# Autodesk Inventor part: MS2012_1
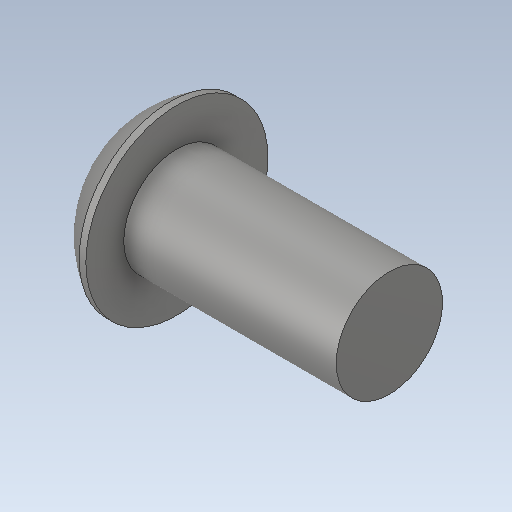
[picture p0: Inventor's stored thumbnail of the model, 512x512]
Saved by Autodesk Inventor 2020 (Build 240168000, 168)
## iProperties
Created: 2015-11
Part Number: MS2012_1
Material: Ogólny
Document SubType Name: Modeling
Designer: Tomasz
Density: 1 g/cm^3
Appearance: Domyślna
Sending System: SolidWorks 2017
Last Author: Tomasz
Last Saved: 2017-09-17
Author: Tomasz
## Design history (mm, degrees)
feature "Imported1"
node "Bryła1"
